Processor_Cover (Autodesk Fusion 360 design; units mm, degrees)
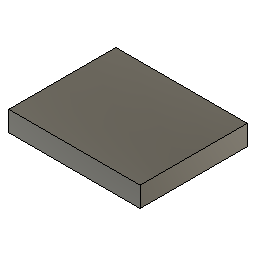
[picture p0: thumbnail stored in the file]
sketch "Sketch1" plane through (0, 0, 0) normal (0, 0, 1) x axis (1, 0, 0)
  line L1 (-13, 0) -> (0, 0)
  line L2 (-13, 10.6) -> (-13, 0)
  line L3 (0, 10.6) -> (-13, 10.6)
  line L4 (0, 0) -> (0, 10.6)
  point P1 (0, 0)
  point P2 (0, 0)
  point P3 (-13, 0)
  point P5 (0, 10.6)
  horizontal L1
  vertical L2
  horizontal L3
  vertical L4
  coincident P1 P2
  dimension "d2" distance P2 P3 = 13 (= "( 13 * Ratio ) * 1 mm")
  dimension "d3" distance P2 P5 = 10.6 (= "( 10.6 * Ratio ) * 1 mm")
extrude "Extrude1" new body sketch "Sketch1" along normal blind 2 (= "( 2 * Ratio ) * 1 mm")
